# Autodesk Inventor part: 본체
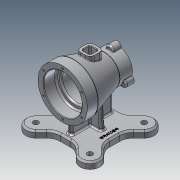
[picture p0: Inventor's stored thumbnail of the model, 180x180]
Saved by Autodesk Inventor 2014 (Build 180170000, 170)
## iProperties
Created: 2018-03
Part Number: 본체
Material: 알루미늄 6061
Document SubType Name: Modeling
Designer: NET
Mass: 1022.3 g
Surface Area: 859.007 cm^2
Volume: 377.231 cm^3
Density: 2.71 g/cm^3
Appearance: 알루미늄 - 평지
Author: NET
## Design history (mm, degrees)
sketch "스케치2"
  geometry: L1 (0, 0)-(100, 0); L2 (0, 0)-(0, 45); L3 (0, 45)-(20, 45); L4 (20, 45)-(77, 27.5); L5 (77, 27.5)-(100, 27.5); L6 (100, 27.5)-(100, 0)
  constraints: 12 end point, 3 perpendicular, 1 horizontal, 1 parallel
  dimensions: "d10" = 100 distance of L1.start L1.end; "d11" = 20 distance of L2.end L3.end; "d12" = 90 diameter of L3 L1; "d13" = 55 diameter of L5 L1; "d14" = 77 horizontal distance of L2.end L4.end
revolve "회전1" sketch "스케치2" stored, may be unused: angle "d15" = 90 deg
sketch "스케치3"
  geometry: L1 (0, 0)-(100, 0); L2 (0, 0)-(0, 35); L3 (0, 35)-(23, 35); L4 (23, 35)-(23, 26); L5 (23, 26)-(70, 26); L6 (70, 26)-(70, 20); L7 (70, 20)-(100, 20); L8 (100, 20)-(100, 0)
  constraints: 16 end point, 5 parallel, 2 perpendicular, 1 horizontal
  dimensions: "d16" = 100 distance of L1.start L1.end; "d17" = 23 distance of L2.end L3.end; "d18" = 47 distance of L4.end L5.end; "d19" = 70 diameter of L3 L1; "d20" = 52 diameter of L5 L1; "d21" = 40 diameter of L7 L1
revolve "회전2" sketch "스케치3" stored, may be unused: angle "d22" = 90 deg
chamfer "모따기1" distance "d23" = 1; stored, may be unused: second distance "d24" = 2, angle "d25" = 45 deg
fillet "모깎기1" dims "d26" = 3
fillet "모깎기2" dims "d27" = 3
chamfer "모따기2" distance "d28" = 1; stored, may be unused: second distance "d29" = 2, angle "d30" = 45 deg
fillet "모깎기3" dims "d31" = 3
node "작업 평면1"
sketch "스케치4"
  geometry: L1 (0, 0)-(-100, 0); L2 (-95, -45)-(-5, -45); L3 (-5, -45)-(-5, 45); L4 (-5, 45)-(-95, 45); L5 (-95, 45)-(-95, -45); L6 (-95, -45)-(-5, 45); L7 (-5, -45)-(-95, 45); 1 further point
  constraints: 14 end point, 3 midpoint, 2 horizontal, 2 parallel, 1 perpendicular
  dimensions: "d50" = 100 distance of L1.start L1.end; "d51" = 90 distance of L3.end L4.end; "d52" = 90 distance of L4.end L2.start
extrude "돌출2" join sketch "스케치4" distance "d53" = 12; taper "d54" = 0 deg
sketch "스케치5"
  geometry: L1 (0, 0)-(-100, 0); L2 (-50, 0)-(-0.503, -49.497); L3 (-5, -45)-(-5, 45) reference; L4 (-95, -45)-(-5, -45) reference; L5 (12.225, -36.77)-(-5, -19.544); L6 (-13.23, -62.225)-(-30.456, -45); L7 (-95, 45)-(-95, -45) reference; L8 (-5, 45)-(-95, 45) reference; L9 (-50, 0)-(-99.497, -49.497); L10 (-50, 0)-(-99.497, 49.497); L11 (-50, 0)-(-0.503, 49.497); L12 (-86.77, -62.225)-(-69.544, -45); L13 (-112.225, -36.77)-(-95.743, -20.287); L14 (12.225, 36.77)-(-5, 19.544); L15 (-13.23, 62.225)-(-30.456, 45); L16 (-86.77, 62.225)-(-69.544, 45); L17 (-112.225, 36.77)-(-95, 19.544); A1 r 70 centre (-50, 0) between (-0.503, -49.497) and (-99.497, -49.497); A2 r 18 centre (-0.503, -49.497) between (12.225, -36.77) and (-13.23, -62.225); A3 r 18 centre (-99.497, -49.497) between (-86.77, -62.225) and (-112.225, -36.77); A4 r 18 centre (-99.497, 49.497) between (-86.77, 62.225) and (-112.225, 36.77); A5 r 18 centre (-0.503, 49.497) between (12.225, 36.77) and (-13.23, 62.225)
  constraints: 26 end point, 12 point on circle, 8 tangent, 7 parallel, 6 point on line, 5 centre point, 4 coincident, 1 horizontal, 1 midpoint, 1 perpendicular
  dimensions: "d55" = 100 distance of L1.start L1.end; "d56" = 140 diameter of A1; "d57" = 45 deg angle of L1 L2; "d58" = 36 diameter of A2; "d61" = 45 deg angle of L1 L9; "d62" = 45 deg angle of L1 L10; "d63" = 45 deg angle of L1 L11; "d64" = 36 diameter of A3; "d65" = 36 diameter of A4; "d66" = 36 diameter of A5
extrude "돌출4" join sketch "스케치5" distance "d68" = 12; taper "d69" = 0 deg
node "작업 평면3"
fillet "모깎기4" dims "d71" = 25
fillet "모깎기5" dims "d72" = 25
fillet "모깎기6" dims "d73" = 25
sketch "스케치6"
  geometry: L1 (0, 0)-(-100, 0); C1 r 5 at (-0.503, -49.497); C2 r 5 at (-99.497, -49.497); C3 r 5 at (-0.503, 49.497); C4 r 5 at (-99.497, 49.497); A1 r 18 centre (-99.497, -49.497) between (-112.225, -36.77) and (-86.77, -62.225) reference; A2 r 18 centre (-0.503, -49.497) between (-13.23, -62.225) and (12.225, -36.77) reference; A3 r 18 centre (-0.503, 49.497) between (12.225, 36.77) and (-13.23, 62.225) reference; A4 r 18 centre (-99.497, 49.497) between (-86.77, 62.225) and (-112.225, 36.77) reference
  constraints: 4 centre point, 4 coincident, 2 end point, 1 horizontal
  dimensions: "d75" = 100 distance of L1.start L1.end; "d76" = 10 diameter of C1; "d77" = 10 diameter of C2; "d78" = 10 diameter of C3; "d79" = 10 diameter of C4
extrude "돌출5" cut sketch "스케치6" stored distance "d80" = 12; taper "d81" = 0 deg
node "작업 평면4"
sketch "스케치8"
  geometry: L1 (0, 0)-(-100, 0); L2 (-37.5, 12.5)-(-62.5, 12.5); L3 (-62.5, 12.5)-(-62.5, -12.5); L4 (-62.5, -12.5)-(-37.5, -12.5); L5 (-37.5, -12.5)-(-37.5, 12.5); L6 (-37.5, 12.5)-(-62.5, -12.5); L7 (-62.5, 12.5)-(-37.5, -12.5); 1 further point
  constraints: 14 end point, 3 midpoint, 2 horizontal, 2 parallel, 1 perpendicular
  dimensions: "d93" = 100 distance of L1.start L1.end; "d94" = 25 distance of L3.end L4.end; "d95" = 25 distance of L2.end L3.end
extrude "돌출7" join sketch "스케치8" stored distance "d96" = 12; taper "d97" = 0 deg
fillet "모깎기11" dims "d98" = 8
fillet "모깎기12" dims "d99" = 1
sketch "스케치9"
  geometry: L1 (0, 0)-(-100, 0); L2 (-42.5, 7.5)-(-57.5, 7.5); L3 (-57.5, 7.5)-(-57.5, -7.5); L4 (-57.5, -7.5)-(-42.5, -7.5); L5 (-42.5, -7.5)-(-42.5, 7.5); L6 (-42.5, 7.5)-(-57.5, -7.5); L7 (-57.5, 7.5)-(-42.5, -7.5); 1 further point
  constraints: 14 end point, 3 midpoint, 2 horizontal, 2 parallel, 1 perpendicular
  dimensions: "d100" = 100 distance of L1.start L1.end; "d101" = 15 distance of L3.end L4.end; "d102" = 15 distance of L4.end L2.start
extrude "돌출8" cut sketch "스케치9" stored distance "d103" = 12; taper "d104" = 0 deg
fillet "모깎기13" dims "d105" = 3
chamfer "모따기3" distance "d106" = 1; stored, may be unused: second distance "d107" = 2, angle "d108" = 45 deg
sketch "스케치11" dims "d118" = 80
  geometry: 3 further points
  constraints: 1 coincident, 1 horizontal alignment, 2 other
hole "구멍1" sketch "스케치11" at (-40, 0) diameter "d119" = 3.242; stored, may be unused: countersink angle "d123" = 90 deg, drill point angle "d125" = 118 deg; dims "d120" = 9, "d121" = 4, "d122" = 2, "d124" = 11
sketch "스케치13"
  geometry: L1 (0, 0)-(27.5, 0); L2 (0, 0)-(-19.093, 33.07); A1 r 27.5 centre (0, 0) between (27.5, 0) and (-13.75, 23.816); A2 r 7 centre (-13.75, 23.816) between (-7.292, 26.516) and (-19.317, 19.573); 1 further point
  constraints: 6 point on circle, 4 end point, 2 centre point, 1 coincident, 1 horizontal, 1 point on line
  dimensions: "d129" = 55 diameter of A1; "d130" = 120 deg angle of L2 L1; "d131" = 14 diameter of A2
extrude "돌출10" join sketch "스케치13" distance "d132" = 15; taper "d133" = 0 deg
fillet "모깎기16" dims "d137" = 3
fillet "모깎기17" dims "d138" = 1
sketch "스케치14"
  geometry: A1 r 7 centre (0, 0) between (-0.127, -6.999) and (-0.127, 6.999) reference; A2 r 7 centre (-41.25, 23.816) between (-35.125, 27.205) and (-47.248, 20.206) reference; A3 r 7 centre (-41.25, -23.816) between (-47.248, -20.206) and (-35.125, -27.205) reference; 2 further points
  constraints: 1 coincident
hole "구멍2" sketch "스케치14" at (0, 0) diameter "d139" = 3.242; stored, may be unused: countersink angle "d143" = 90 deg, drill point angle "d145" = 118 deg; dims "d140" = 9, "d141" = 4, "d142" = 2, "d144" = 11
sketch "스케치15"
  geometry: L1 (-86.77, -62.225)-(-76.866, -52.322) reference; L2 (-102.322, -26.866)-(-112.225, -36.77) reference; L3 (-95, 9.189)-(-95, -9.189) reference; L4 (-112.225, 36.77)-(-102.322, 26.866) reference; L5 (-76.866, 52.322)-(-86.77, 62.225) reference; L6 (-40.811, 45)-(-59.189, 45) reference; L7 (-23.134, 52.322)-(-13.23, 62.225) reference; L8 (12.225, 36.77)-(2.322, 26.866) reference; L9 (-5, -9.189)-(-5, 9.189) reference; L10 (2.322, -26.866)-(12.225, -36.77) reference; L11 (-13.23, -62.225)-(-23.134, -52.322) reference; L12 (-59.189, -45)-(-40.811, -45) reference; L13 (0, 0)-(-100, 0); C1 r 5 at (-0.503, 49.497) reference; C2 r 5 at (-0.503, -49.497) reference; C3 r 5 at (-99.497, -49.497) reference; C4 r 5 at (-99.497, 49.497) reference; A1 r 18 centre (-99.497, -49.497) between (-112.225, -36.77) and (-86.77, -62.225) reference; A2 r 25 centre (-120, -9.189) between (-102.322, -26.866) and (-95, -9.189) reference; A3 r 25 centre (-120, 9.189) between (-95, 9.189) and (-102.322, 26.866) reference; A4 r 18 centre (-99.497, 49.497) between (-86.77, 62.225) and (-112.225, 36.77) reference; A5 r 25 centre (-59.189, 70) between (-76.866, 52.322) and (-59.189, 45) reference; A6 r 25 centre (-40.811, 70) between (-40.811, 45) and (-23.134, 52.322) reference; A7 r 18 centre (-0.503, 49.497) between (12.225, 36.77) and (-13.23, 62.225) reference; A8 r 25 centre (20, 9.189) between (2.322, 26.866) and (-5, 9.189) reference; A9 r 25 centre (20, -9.189) between (-5, -9.189) and (2.322, -26.866) reference; A10 r 18 centre (-0.503, -49.497) between (-13.23, -62.225) and (12.225, -36.77) reference; A11 r 25 centre (-40.811, -70) between (-23.134, -52.322) and (-40.811, -45) reference; A12 r 25 centre (-59.189, -70) between (-59.189, -45) and (-76.866, -52.322) reference; 1 further point
  constraints: 2 end point, 1 parallel, 1 other
  dimensions: "d149" = 100 distance of L13.start L13.end; "d150" = 35 vertical distance of L13.start point (-50, 35); "d151" = 50 horizontal distance of L13.start point (-50, 35)
extrude "돌출11" join sketch "스케치15" distance "d152" = 0.5; taper "d153" = 0 deg
chamfer "모따기4" distance "d154" = 3; stored, may be unused: second distance "d155" = 2, angle "d156" = 45 deg
sketch "스케치16"
  geometry: L1 (0, 0)-(-100, 0); L2 (-87, 4)-(-13, 4); L3 (-13, 4)-(-13, -4); L4 (-13, -4)-(-87, -4); L5 (-87, -4)-(-87, 4); L6 (-87, 4)-(-13, -4); L7 (-13, 4)-(-87, -4); 1 further point
  constraints: 14 end point, 3 midpoint, 2 horizontal, 2 parallel, 1 perpendicular
  dimensions: "d157" = 100 distance of L1.start L1.end; "d158" = 8 distance of L2.end L3.end; "d159" = 37 horizontal distance of L3.end point (-50, 0)
extrude "돌출12" join sketch "스케치16" stored distance "d160" = 10; taper "d161" = 0 deg
node "작업 평면5"
sketch "스케치17"
  geometry: L1 (28.988, -70)-(9.189, -70) reference; L2 (20.467, -29.616)-(24, -70); L3 (0, 0)-(0, -76.861); 1 further point
  constraints: 4 end point, 1 perpendicular, 1 point on line, 2 other
  dimensions: "d163" = 24 horizontal distance of L2.end L3.end; "d164" = 95 deg angle of L1 L2
feature "리브1" sketch "스케치17" dims "d165" = 1, "d166" = 8, "d167" = 0, "d168" = 0, "d169" = 1, "d170" = 1
sketch "스케치18"
  geometry: L1 (-9.189, -70)-(-28.988, -70) reference; L2 (-20.467, -29.616)-(-24, -70); L3 (0, 0)-(0, -75.696); 1 further point
  constraints: 4 end point, 1 perpendicular, 1 point on line, 2 other
  dimensions: "d171" = 24 horizontal distance of L3.end L2.end; "d172" = 95 deg angle of L1 L2
feature "리브2" sketch "스케치18" dims "d173" = 1, "d174" = 8, "d175" = 0, "d176" = 0, "d177" = 1, "d178" = 1
fillet "모깎기18" dims "d179" = 3
fillet "모깎기19" dims "d180" = 3
node "솔리드2"
mirror "대칭1"
pattern_circular "원형 패턴2" dims angle "d127" = 360 deg
pattern_circular "원형 패턴3" dims angle "d135" = 360 deg
pattern_circular "원형 패턴4" dims angle "d147" = 360 deg
node "투영된 루프1"
other parameters: "d32" = -82, "d92" = 45
